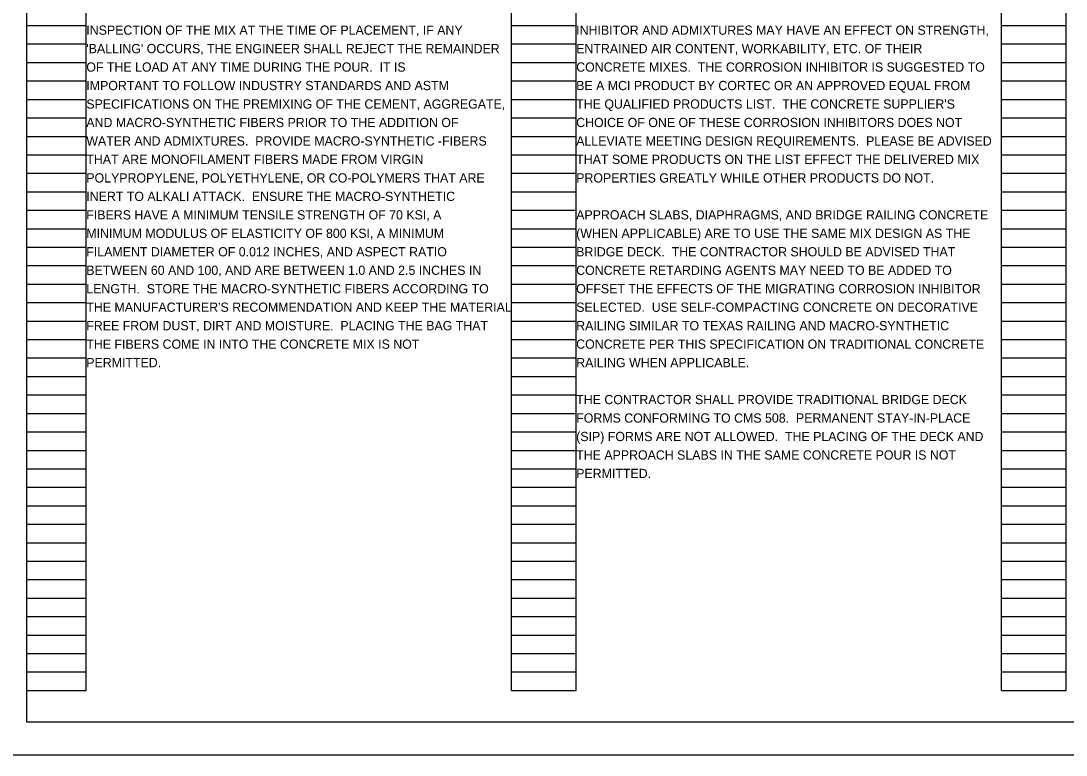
# Model space of a CAD drawing. Extents: x -14.8 to 34, y 0 to 43.2.
# Drawn here: x 1.91 to 17.74, y 0 to 11.13 of the extents above; entities that cross this region are included whole.
import ezdxf

# ---------------------------------------------------------------- set-up
doc = ezdxf.new("R2010")
doc.units = 0
for name, color, linetype in [('SH_Border', 7, 'Continuous'), ('SH_Cut_Line', 7, 'Continuous'), ('SH_Data', 7, 'Continuous'), ('SH_Text', 7, 'Continuous')]:
    doc.layers.add(name, color=color, linetype=linetype)

msp = doc.modelspace()

# ---------------------------------------------------------------- linework, layer by layer
at = {"layer": 'SH_Border'}
msp.add_lwpolyline([(2, 21.5), (33.5, 21.5), (33.5, 0.5), (2, 0.5)], close=True, dxfattribs=at)
at = {"layer": 'SH_Cut_Line'}
msp.add_lwpolyline([(0, 22), (34, 22), (34, 0), (0, 0)], close=True, dxfattribs=at)
at = {"layer": 'SH_Data'}
for p, q in [((2, 0.98), (2, 21.14)), ((2.9, 0.98), (2.9, 21.14)), ((9.34, 0.98), (9.34, 21.14)), ((10.32, 0.98), (10.32, 21.14)), ((16.76, 0.98), (16.76, 21.14)), ((17.74, 0.98), (17.74, 21.14)), ((2, 11.06), (2.9, 11.06)), ((9.34, 11.06), (10.32, 11.06)), ((16.76, 11.06), (17.74, 11.06)), ((2, 10.78), (2.9, 10.78)), ((9.34, 10.78), (10.32, 10.78)), ((16.76, 10.78), (17.74, 10.78)), ((2, 10.5), (2.9, 10.5)), ((9.34, 10.5), (10.32, 10.5)), ((16.76, 10.5), (17.74, 10.5)), ((2, 10.22), (2.9, 10.22)), ((9.34, 10.22), (10.32, 10.22)), ((16.76, 10.22), (17.74, 10.22)), ((2, 9.94), (2.9, 9.94)), ((9.34, 9.94), (10.32, 9.94)), ((16.76, 9.94), (17.74, 9.94)), ((2, 9.66), (2.9, 9.66)), ((9.34, 9.66), (10.32, 9.66)), ((16.76, 9.66), (17.74, 9.66)), ((2, 9.38), (2.9, 9.38)), ((9.34, 9.38), (10.32, 9.38)), ((16.76, 9.38), (17.74, 9.38)), ((2, 9.1), (2.9, 9.1)), ((9.34, 9.1), (10.32, 9.1)), ((16.76, 9.1), (17.74, 9.1)), ((2, 8.82), (2.9, 8.82)), ((9.34, 8.82), (10.32, 8.82)), ((16.76, 8.82), (17.74, 8.82)), ((2, 8.54), (2.9, 8.54)), ((9.34, 8.54), (10.32, 8.54)), ((16.76, 8.54), (17.74, 8.54)), ((2, 8.26), (2.9, 8.26)), ((9.34, 8.26), (10.32, 8.26)), ((16.76, 8.26), (17.74, 8.26)), ((2, 7.98), (2.9, 7.98)), ((9.34, 7.98), (10.32, 7.98)), ((16.76, 7.98), (17.74, 7.98)), ((2, 7.7), (2.9, 7.7)), ((9.34, 7.7), (10.32, 7.7)), ((16.76, 7.7), (17.74, 7.7)), ((2, 7.42), (2.9, 7.42)), ((9.34, 7.42), (10.32, 7.42)), ((16.76, 7.42), (17.74, 7.42)), ((2, 7.14), (2.9, 7.14)), ((9.34, 7.14), (10.32, 7.14)), ((16.76, 7.14), (17.74, 7.14)), ((2, 6.86), (2.9, 6.86)), ((9.34, 6.86), (10.32, 6.86)), ((16.76, 6.86), (17.74, 6.86)), ((2, 6.58), (2.9, 6.58)), ((9.34, 6.58), (10.32, 6.58)), ((16.76, 6.58), (17.74, 6.58)), ((2, 6.3), (2.9, 6.3)), ((9.34, 6.3), (10.32, 6.3)), ((16.76, 6.3), (17.74, 6.3)), ((2, 6.02), (2.9, 6.02)), ((9.34, 6.02), (10.32, 6.02)), ((16.76, 6.02), (17.74, 6.02)), ((2, 5.74), (2.9, 5.74)), ((9.34, 5.74), (10.32, 5.74)), ((16.76, 5.74), (17.74, 5.74)), ((2, 5.46), (2.9, 5.46)), ((9.34, 5.46), (10.32, 5.46)), ((16.76, 5.46), (17.74, 5.46)), ((2, 5.18), (2.9, 5.18)), ((9.34, 5.18), (10.32, 5.18)), ((16.76, 5.18), (17.74, 5.18)), ((2, 4.9), (2.9, 4.9)), ((9.34, 4.9), (10.32, 4.9)), ((16.76, 4.9), (17.74, 4.9)), ((2, 4.62), (2.9, 4.62)), ((9.34, 4.62), (10.32, 4.62)), ((16.76, 4.62), (17.74, 4.62)), ((2, 4.34), (2.9, 4.34)), ((9.34, 4.34), (10.32, 4.34)), ((16.76, 4.34), (17.74, 4.34)), ((2, 4.06), (2.9, 4.06)), ((9.34, 4.06), (10.32, 4.06)), ((16.76, 4.06), (17.74, 4.06)), ((2, 3.78), (2.9, 3.78)), ((9.34, 3.78), (10.32, 3.78)), ((16.76, 3.78), (17.74, 3.78)), ((2, 3.5), (2.9, 3.5)), ((9.34, 3.5), (10.32, 3.5)), ((16.76, 3.5), (17.74, 3.5)), ((2, 3.22), (2.9, 3.22)), ((9.34, 3.22), (10.32, 3.22)), ((16.76, 3.22), (17.74, 3.22)), ((2, 2.94), (2.9, 2.94)), ((9.34, 2.94), (10.32, 2.94)), ((16.76, 2.94), (17.74, 2.94)), ((2, 2.66), (2.9, 2.66)), ((9.34, 2.66), (10.32, 2.66)), ((16.76, 2.66), (17.74, 2.66)), ((2, 2.38), (2.9, 2.38)), ((9.34, 2.38), (10.32, 2.38)), ((16.76, 2.38), (17.74, 2.38)), ((2, 2.1), (2.9, 2.1)), ((9.34, 2.1), (10.32, 2.1)), ((16.76, 2.1), (17.74, 2.1)), ((2, 1.82), (2.9, 1.82)), ((9.34, 1.82), (10.32, 1.82)), ((16.76, 1.82), (17.74, 1.82)), ((2, 1.54), (2.9, 1.54)), ((9.34, 1.54), (10.32, 1.54)), ((16.76, 1.54), (17.74, 1.54)), ((2, 1.26), (2.9, 1.26)), ((9.34, 1.26), (10.32, 1.26)), ((16.76, 1.26), (17.74, 1.26)), ((2, 0.98), (2.9, 0.98)), ((9.34, 0.98), (10.32, 0.98)), ((16.76, 0.98), (17.74, 0.98))]:
    msp.add_line(p, q, dxfattribs=at)

# ---------------------------------------------------------------- texts
at = {"layer": 'SH_Text'}
for s, p in [('INSPECTION OF THE MIX AT THE TIME OF PLACEMENT, IF ANY ', (2.9, 10.92)), ('INHIBITOR AND ADMIXTURES MAY HAVE AN EFFECT ON STRENGTH, ', (10.32, 10.92)), ("'BALLING' OCCURS, THE ENGINEER SHALL REJECT THE REMAINDER ", (2.9, 10.64)), ('ENTRAINED AIR CONTENT, WORKABILITY, ETC. OF THEIR ', (10.32, 10.64)), ('OF THE LOAD AT ANY TIME DURING THE POUR.  IT IS ', (2.9, 10.36)), ('CONCRETE MIXES.  THE CORROSION INHIBITOR IS SUGGESTED TO ', (10.32, 10.36)), ('IMPORTANT TO FOLLOW INDUSTRY STANDARDS AND ASTM ', (2.9, 10.08)), ('BE A MCI PRODUCT BY CORTEC OR AN APPROVED EQUAL FROM ', (10.32, 10.08)), ('SPECIFICATIONS ON THE PREMIXING OF THE CEMENT, AGGREGATE, ', (2.9, 9.8)), ("THE QUALIFIED PRODUCTS LIST.  THE CONCRETE SUPPLIER'S ", (10.32, 9.8)), ('AND MACRO-SYNTHETIC FIBERS PRIOR TO THE ADDITION OF ', (2.9, 9.52)), ('CHOICE OF ONE OF THESE CORROSION INHIBITORS DOES NOT ', (10.32, 9.52)), ('WATER AND ADMIXTURES.  PROVIDE MACRO-SYNTHETIC -FIBERS ', (2.9, 9.24)), ('ALLEVIATE MEETING DESIGN REQUIREMENTS.  PLEASE BE ADVISED ', (10.32, 9.24)), ('THAT ARE MONOFILAMENT FIBERS MADE FROM VIRGIN ', (2.9, 8.96)), ('THAT SOME PRODUCTS ON THE LIST EFFECT THE DELIVERED MIX ', (10.32, 8.96)), ('POLYPROPYLENE, POLYETHYLENE, OR CO-POLYMERS THAT ARE ', (2.9, 8.68)), ('PROPERTIES GREATLY WHILE OTHER PRODUCTS DO NOT.', (10.32, 8.68)), ('INERT TO ALKALI ATTACK.  ENSURE THE MACRO-SYNTHETIC ', (2.9, 8.4)), ('FIBERS HAVE A MINIMUM TENSILE STRENGTH OF 70 KSI, A ', (2.9, 8.12)), ('APPROACH SLABS, DIAPHRAGMS, AND BRIDGE RAILING CONCRETE ', (10.32, 8.12)), ('MINIMUM MODULUS OF ELASTICITY OF 800 KSI, A MINIMUM ', (2.9, 7.84)), ('(WHEN APPLICABLE) ARE TO USE THE SAME MIX DESIGN AS THE ', (10.32, 7.84)), ('FILAMENT DIAMETER OF 0.012 INCHES, AND ASPECT RATIO ', (2.9, 7.56)), ('BRIDGE DECK.  THE CONTRACTOR SHOULD BE ADVISED THAT ', (10.32, 7.56)), ('BETWEEN 60 AND 100, AND ARE BETWEEN 1.0 AND 2.5 INCHES IN ', (2.9, 7.28)), ('CONCRETE RETARDING AGENTS MAY NEED TO BE ADDED TO ', (10.32, 7.28)), ('LENGTH.  STORE THE MACRO-SYNTHETIC FIBERS ACCORDING TO ', (2.9, 7)), ('OFFSET THE EFFECTS OF THE MIGRATING CORROSION INHIBITOR ', (10.32, 7)), ("THE MANUFACTURER'S RECOMMENDATION AND KEEP THE MATERIAL ", (2.9, 6.72)), ('SELECTED.  USE SELF-COMPACTING CONCRETE ON DECORATIVE ', (10.32, 6.72)), ('FREE FROM DUST, DIRT AND MOISTURE.  PLACING THE BAG THAT ', (2.9, 6.44)), ('RAILING SIMILAR TO TEXAS RAILING AND MACRO-SYNTHETIC ', (10.32, 6.44)), ('THE FIBERS COME IN INTO THE CONCRETE MIX IS NOT ', (2.9, 6.16)), ('CONCRETE PER THIS SPECIFICATION ON TRADITIONAL CONCRETE ', (10.32, 6.16)), ('PERMITTED.', (2.9, 5.88)), ('RAILING WHEN APPLICABLE.', (10.32, 5.88)), ('THE CONTRACTOR SHALL PROVIDE TRADITIONAL BRIDGE DECK ', (10.32, 5.32)), ('FORMS CONFORMING TO CMS 508.  PERMANENT STAY-IN-PLACE ', (10.32, 5.04)), ('(SIP) FORMS ARE NOT ALLOWED.  THE PLACING OF THE DECK AND ', (10.32, 4.76)), ('THE APPROACH SLABS IN THE SAME CONCRETE POUR IS NOT ', (10.32, 4.48)), ('PERMITTED.', (10.32, 4.2))]:
    msp.add_text(s, height=0.14, dxfattribs=at).set_placement(p)

doc.saveas('drawing.dxf')
